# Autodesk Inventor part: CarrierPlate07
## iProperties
Created: 2008-02
Part Number: CarrierPlate07
Document SubType Name: Modeling
Designer: grh
Density: 1 g/cm^3
Author: grh
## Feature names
1. Extrusion1
